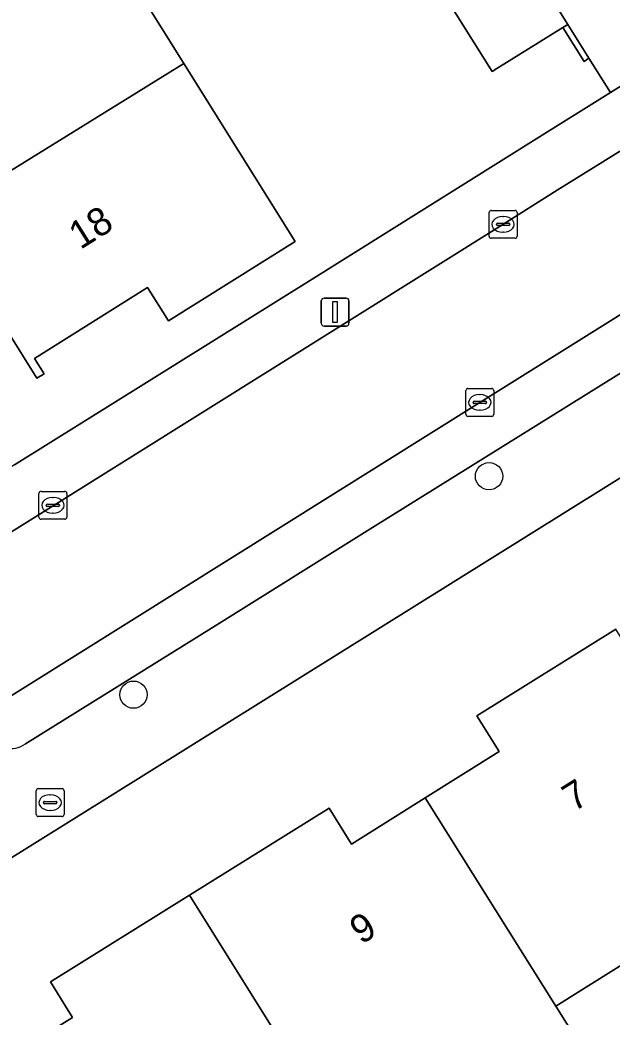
# Model space of a CAD drawing. Extents: x 158835 to 160077, y 386387 to 387778.
# Drawn here: x 159068.07 to 159089.27, y 387041.53 to 387077.25 of the extents above; entities that cross this region are included whole.
import ezdxf

# ---------------------------------------------------------------- set-up
doc = ezdxf.new("R2010")
doc.units = 0
for name, color, linetype in [('IMGEO_Boom', 7, 'Continuous'), ('IMGEO_Brandkraan', 7, 'Continuous'), ('IMGEO_Erf', 7, 'Continuous'), ('IMGEO_Kolk', 7, 'Continuous'), ('IMGEO_Lichtmast', 7, 'Continuous'), ('IMGEO_Muur', 7, 'Continuous'), ('IMGEO_Pand', 7, 'Continuous'), ('IMGEO_Pand_nummerreeks', 7, 'Continuous'), ('IMGEO_Parkeervlak_open', 7, 'Continuous'), ('IMGEO_Rijbaan_lokaal_open', 7, 'Continuous'), ('IMGEO_Voetpad_open', 7, 'Continuous')]:
    doc.layers.add(name, color=color, linetype=linetype)

msp = doc.modelspace()

# ---------------------------------------------------------------- linework, layer by layer
at = {"layer": 'IMGEO_Boom'}
for centre in [(159084.862, 387060.901), (159072.133, 387053.077)]:
    msp.add_circle(centre, 0.489, dxfattribs=at)
at = {"layer": 'IMGEO_Brandkraan'}
for p, q in [((159068.649, 387048.786), (159068.649, 387049.638)), ((159068.724, 387049.712), (159069.576, 387049.712)), ((159069.137, 387049.492), (159069.162, 387049.492)), ((159069.65, 387049.638), (159069.65, 387048.786)), ((159068.908, 387049.206), (159068.908, 387049.218)), ((159069.346, 387049.169), (159068.948, 387049.169)), ((159068.951, 387049.255), (159069.349, 387049.255)), ((159069.392, 387049.218), (159069.392, 387049.206)), ((159069.16, 387048.932), (159069.135, 387048.932)), ((159069.576, 387048.712), (159068.724, 387048.712))]:
    msp.add_line(p, q, dxfattribs=at)
for points in [[(159068.649, 387048.786), (159068.649, 387049.638)], [(159068.724, 387049.712), (159069.576, 387049.712)], [(159069.65, 387049.638), (159069.65, 387048.786)], [(159069.576, 387048.712), (159068.724, 387048.712)]]:
    msp.add_lwpolyline(points, dxfattribs=at)
for centre, radius, start, end in [((159068.726, 387049.636), 0.0765, 91.552, 178.448), ((159068.726, 387049.636), 0.0765, 91.552, 178.448), ((159069.574, 387049.636), 0.0765, 1.552, 88.448), ((159069.574, 387049.636), 0.0765, 1.552, 88.448), ((159068.948, 387049.215), 0.0403, 85.8775, 175.7526), ((159068.945, 387049.205), 0.0366, 178.938, 274.7102), ((159069.349, 387049.212), 0.043, 264.8664, 352.4533), ((159069.353, 387049.217), 0.0386, 1.7309, 96.639), ((159068.726, 387048.788), 0.0765, 181.552, 268.448), ((159068.726, 387048.788), 0.0765, 181.552, 268.448), ((159069.574, 387048.788), 0.0765, 271.552, 358.448), ((159069.574, 387048.788), 0.0765, 271.552, 358.448)]:
    msp.add_arc(centre, radius, start, end, dxfattribs=at)
for centre, major_axis, ratio, start_param, end_param in [((159069.136, 387049.212), (-0.387, 0.002), 0.722429, 4.712389, 7.853982), ((159069.161, 387049.212), (-0.39, 0.002), 0.717154, 1.570796, 4.712389)]:
    msp.add_ellipse(centre, major_axis=major_axis, ratio=ratio, start_param=start_param, end_param=end_param, dxfattribs=at)
at = {"layer": 'IMGEO_Erf'}
for points in [[(159067.868, 387061.308), (159078.525, 387067.969), (159086.674, 387073.064), (159089.207, 387074.648), (159088.441, 387075.876), (159088.263, 387075.765), (159087.506, 387076.978), (159085.147, 387075.505), (159084.978, 387075.399), (159081.697, 387080.65), (159084.403, 387082.34), (159074.494, 387097.991), (159071.028, 387103.53), (159070.62, 387104.158), (159061.621, 387118.5)], [(159069.015, 387083.564), (159073.932, 387075.693), (159077.921, 387069.308), (159073.386, 387066.475), (159072.636, 387067.668), (159068.594, 387065.126), (159068.939, 387064.576), (159068.677, 387064.411), (159065.13, 387070.084), (159064.091, 387069.434), (159064.021, 387069.549), (159063.927, 387069.706), (159064.962, 387070.353), (159060.221, 387077.938)], [(159110.736, 387074.06), (159063.193, 387044.393)], [(159062.71, 387041.605), (159065.419, 387037.291), (159067.725, 387038.732), (159067.005, 387039.886), (159067.275, 387040.054), (159067.37, 387039.902), (159069.951, 387041.51), (159069.158, 387042.784), (159074.14, 387045.892), (159079.133, 387049.006), (159079.934, 387047.727), (159082.578, 387049.382), (159085.221, 387051.036), (159084.42, 387052.315), (159089.398, 387055.425)], [(159094.861, 387046.679), (159087.251, 387041.923), (159088.84, 387039.38), (159081.208, 387034.61), (159079.6, 387037.141), (159071.774, 387032.25), (159071.762, 387032.269), (159069.441, 387030.819), (159076.524, 387019.468), (159125.496, 386940.988)]]:
    msp.add_lwpolyline(points, dxfattribs=at)
at = {"layer": 'IMGEO_Kolk'}
for p, q in [((159084.865, 387069.501), (159084.865, 387070.353)), ((159084.94, 387070.427), (159085.792, 387070.427)), ((159085.353, 387070.207), (159085.378, 387070.207)), ((159085.866, 387070.353), (159085.866, 387069.501)), ((159085.124, 387069.921), (159085.124, 387069.933)), ((159085.562, 387069.884), (159085.164, 387069.884)), ((159085.167, 387069.97), (159085.565, 387069.97)), ((159085.608, 387069.933), (159085.608, 387069.921)), ((159085.376, 387069.647), (159085.351, 387069.647)), ((159085.792, 387069.427), (159084.94, 387069.427)), ((159084.032, 387063.122), (159084.032, 387063.974)), ((159084.107, 387064.048), (159084.959, 387064.048)), ((159084.52, 387063.828), (159084.545, 387063.828)), ((159085.033, 387063.974), (159085.033, 387063.122)), ((159084.291, 387063.542), (159084.291, 387063.554)), ((159084.729, 387063.505), (159084.331, 387063.505)), ((159084.334, 387063.591), (159084.732, 387063.591)), ((159084.775, 387063.554), (159084.775, 387063.542)), ((159084.959, 387063.048), (159084.107, 387063.048)), ((159084.543, 387063.268), (159084.518, 387063.268)), ((159068.747, 387059.436), (159068.747, 387060.288)), ((159068.822, 387060.362), (159069.674, 387060.362)), ((159069.748, 387060.288), (159069.748, 387059.436)), ((159069.006, 387059.856), (159069.006, 387059.868)), ((159069.049, 387059.905), (159069.447, 387059.905)), ((159069.235, 387060.142), (159069.26, 387060.142)), ((159069.49, 387059.868), (159069.49, 387059.856)), ((159069.444, 387059.819), (159069.046, 387059.819)), ((159069.258, 387059.582), (159069.233, 387059.582)), ((159069.674, 387059.362), (159068.822, 387059.362))]:
    msp.add_line(p, q, dxfattribs=at)
for points in [[(159084.865, 387069.501), (159084.865, 387070.353)], [(159084.94, 387070.427), (159085.792, 387070.427)], [(159085.866, 387070.353), (159085.866, 387069.501)], [(159085.792, 387069.427), (159084.94, 387069.427)], [(159084.032, 387063.122), (159084.032, 387063.974)], [(159084.107, 387064.048), (159084.959, 387064.048)], [(159085.033, 387063.974), (159085.033, 387063.122)], [(159084.959, 387063.048), (159084.107, 387063.048)], [(159068.747, 387059.436), (159068.747, 387060.288)], [(159068.822, 387060.362), (159069.674, 387060.362)], [(159069.748, 387060.288), (159069.748, 387059.436)], [(159069.674, 387059.362), (159068.822, 387059.362)]]:
    msp.add_lwpolyline(points, dxfattribs=at)
for centre, radius, start, end in [((159084.942, 387070.351), 0.0765, 91.552, 178.448), ((159084.942, 387070.351), 0.0765, 91.552, 178.448), ((159085.79, 387070.351), 0.0765, 1.552, 88.448), ((159085.79, 387070.351), 0.0765, 1.552, 88.448), ((159085.164, 387069.93), 0.0403, 85.8775, 175.7526), ((159085.161, 387069.92), 0.0366, 178.938, 274.7102), ((159085.565, 387069.927), 0.043, 264.8664, 352.4533), ((159085.569, 387069.932), 0.0386, 1.7309, 96.639), ((159084.942, 387069.503), 0.0765, 181.552, 268.448), ((159084.942, 387069.503), 0.0765, 181.552, 268.448), ((159085.79, 387069.503), 0.0765, 271.552, 358.448), ((159085.79, 387069.503), 0.0765, 271.552, 358.448), ((159084.109, 387063.972), 0.0765, 91.552, 178.448), ((159084.109, 387063.972), 0.0765, 91.552, 178.448), ((159084.957, 387063.972), 0.0765, 1.552, 88.448), ((159084.957, 387063.972), 0.0765, 1.552, 88.448), ((159084.331, 387063.551), 0.0403, 85.8775, 175.7526), ((159084.328, 387063.541), 0.0366, 178.938, 274.7102), ((159084.732, 387063.548), 0.043, 264.8664, 352.4533), ((159084.736, 387063.553), 0.0386, 1.7309, 96.639), ((159084.109, 387063.124), 0.0765, 181.552, 268.448), ((159084.109, 387063.124), 0.0765, 181.552, 268.448), ((159084.957, 387063.124), 0.0765, 271.552, 358.448), ((159084.957, 387063.124), 0.0765, 271.552, 358.448), ((159068.824, 387060.286), 0.0765, 91.552, 178.448), ((159068.824, 387060.286), 0.0765, 91.552, 178.448), ((159069.672, 387060.286), 0.0765, 1.552, 88.448), ((159069.672, 387060.286), 0.0765, 1.552, 88.448), ((159069.046, 387059.865), 0.0403, 85.8775, 175.7526), ((159069.043, 387059.855), 0.0366, 178.938, 274.7102), ((159069.447, 387059.862), 0.043, 264.8664, 352.4533), ((159069.451, 387059.867), 0.0386, 1.7309, 96.639), ((159068.824, 387059.438), 0.0765, 181.552, 268.448), ((159068.824, 387059.438), 0.0765, 181.552, 268.448), ((159069.672, 387059.438), 0.0765, 271.552, 358.448), ((159069.672, 387059.438), 0.0765, 271.552, 358.448)]:
    msp.add_arc(centre, radius, start, end, dxfattribs=at)
for centre, major_axis, ratio, start_param, end_param in [((159085.352, 387069.927), (-0.387, 0.002), 0.722429, 4.712389, 7.853982), ((159085.377, 387069.927), (-0.39, 0.002), 0.717154, 1.570796, 4.712389), ((159084.519, 387063.548), (-0.387, 0.002), 0.722429, 4.712389, 7.853982), ((159084.544, 387063.548), (-0.39, 0.002), 0.717154, 1.570796, 4.712389), ((159069.234, 387059.862), (-0.387, 0.002), 0.722429, 4.712389, 7.853982), ((159069.259, 387059.862), (-0.39, 0.002), 0.717154, 1.570796, 4.712389)]:
    msp.add_ellipse(centre, major_axis=major_axis, ratio=ratio, start_param=start_param, end_param=end_param, dxfattribs=at)
at = {"layer": 'IMGEO_Lichtmast'}
for p, q in [((159078.855, 387066.383), (159078.855, 387067.183)), ((159078.855, 387067.183), (159078.855, 387066.383)), ((159078.955, 387067.283), (159079.745, 387067.283)), ((159079.745, 387067.283), (159078.955, 387067.283)), ((159079.845, 387067.183), (159079.845, 387066.383)), ((159079.845, 387066.383), (159079.845, 387067.183)), ((159079.745, 387066.283), (159078.955, 387066.283)), ((159078.955, 387066.283), (159079.745, 387066.283))]:
    msp.add_line(p, q, dxfattribs=at)
msp.add_lwpolyline([(159079.275, 387067.158), (159079.425, 387067.158), (159079.425, 387066.408), (159079.275, 387066.408), (159079.275, 387067.158)], dxfattribs=at)
for centre, start, end in [((159078.955, 387067.183), 90, 180), ((159078.955, 387067.183), 90, 180), ((159079.745, 387067.183), 0, 90), ((159079.745, 387067.183), 360, 90), ((159078.955, 387066.383), 180, 270), ((159078.955, 387066.383), 180, 270), ((159079.745, 387066.383), 270, 0), ((159079.745, 387066.383), 270, 0)]:
    msp.add_arc(centre, 0.1, start, end, dxfattribs=at)
at = {"layer": 'IMGEO_Muur'}
msp.add_lwpolyline([(159087.506, 387076.978), (159088.263, 387075.765), (159088.441, 387075.876), (159087.684, 387077.089)], close=True, dxfattribs=at)
msp.add_lwpolyline([(159078.525, 387067.969), (159086.674, 387073.064)], dxfattribs=at)
at = {"layer": 'IMGEO_Pand'}
for points in [[(159073.932, 387075.693), (159069.015, 387083.564), (159059.111, 387077.412), (159059.184, 387077.29), (159060.221, 387077.938), (159064.962, 387070.353), (159063.927, 387069.706), (159064.021, 387069.549)], [(159087.684, 387077.089), (159084.403, 387082.34), (159081.697, 387080.65), (159084.978, 387075.399), (159085.147, 387075.505), (159087.506, 387076.978)], [(159064.021, 387069.549), (159064.091, 387069.434), (159065.13, 387070.084), (159068.677, 387064.411), (159068.939, 387064.576), (159068.594, 387065.126), (159072.636, 387067.668), (159073.386, 387066.475), (159077.921, 387069.308), (159073.932, 387075.693)], [(159087.251, 387041.923), (159094.861, 387046.679), (159089.398, 387055.425), (159084.42, 387052.315), (159085.221, 387051.036), (159082.578, 387049.382)], [(159079.6, 387037.141), (159081.208, 387034.61), (159088.84, 387039.38), (159087.251, 387041.923), (159082.578, 387049.382), (159079.934, 387047.727), (159079.133, 387049.006), (159074.14, 387045.892)], [(159069.441, 387030.819), (159071.762, 387032.269), (159071.774, 387032.25), (159079.6, 387037.141), (159074.14, 387045.892), (159069.158, 387042.784), (159069.951, 387041.51), (159067.37, 387039.902), (159067.275, 387040.054), (159067.005, 387039.886), (159067.725, 387038.732), (159065.419, 387037.291)]]:
    msp.add_lwpolyline(points, close=True, dxfattribs=at)
at = {"layer": 'IMGEO_Parkeervlak_open'}
for points in [[(159110.593, 387079.859), (159103.151, 387075.188), (159084.528, 387063.55), (159066.593, 387052.325), (159064.66, 387051.128)], [(159068.268, 387051.318), (159074.93, 387055.455), (159080.693, 387059.061), (159090.042, 387064.897), (159095.791, 387068.486), (159105.146, 387074.32), (159108.343, 387076.314), (159108.9, 387076.666)]]:
    msp.add_lwpolyline(points, dxfattribs=at)
msp.add_arc((159067.731, 387052.067), 0.922, 256.753, 305.631, dxfattribs=at)
at = {"layer": 'IMGEO_Rijbaan_lokaal_open'}
msp.add_lwpolyline([(159140.304, 387104.262), (159137.382, 387102.443), (159121.021, 387092.233), (159104.81, 387082.095), (159090.415, 387073.084), (159087.209, 387071.089), (159085.362, 387069.926), (159066.482, 387058.108), (159057.993, 387052.813), (159060.695, 387048.588), (159061.454, 387049.086), (159064.66, 387051.128), (159066.593, 387052.325), (159084.528, 387063.55), (159103.151, 387075.188), (159110.593, 387079.859), (159110.704, 387079.928), (159119.193, 387085.238), (159119.416, 387085.378), (159123.735, 387088.075), (159139.7, 387098.006), (159145.108, 387101.404), (159145.475, 387101.632), (159152.358, 387105.91)], dxfattribs=at)
at = {"layer": 'IMGEO_Voetpad_open'}
for points in [[(159143.08, 387108.388), (159140.091, 387106.463), (159092.005, 387076.397), (159089.207, 387074.648), (159086.674, 387073.064), (159078.525, 387067.969), (159067.868, 387061.308), (159063.036, 387058.319), (159058.826, 387055.683), (159056.14, 387053.974), (159055.192, 387053.386), (159050.577, 387050.525), (159048.428, 387049.192), (159052.552, 387042.529), (159052.677, 387042.36)], [(159058.932, 387041.754), (159063.193, 387044.393), (159110.736, 387074.06), (159110.756, 387074.075), (159115.626, 387077.064), (159119.918, 387079.72), (159122.014, 387081.038), (159141.336, 387093.187)], [(159054.603, 387050.681), (159056.255, 387051.72), (159057.993, 387052.813), (159057.411, 387053.746), (159065.9, 387059.041), (159066.482, 387058.108), (159085.362, 387069.926), (159087.209, 387071.089), (159090.415, 387073.084), (159104.81, 387082.095)], [(159108.9, 387076.666), (159108.343, 387076.314), (159105.146, 387074.32), (159095.791, 387068.486), (159090.042, 387064.897), (159080.693, 387059.061), (159074.93, 387055.455), (159068.268, 387051.318)]]:
    msp.add_lwpolyline(points, dxfattribs=at)
msp.add_lwpolyline([(159074.287, 387104.756), (159073.536, 387105.956), (159070.62, 387104.158), (159071.028, 387103.53), (159074.494, 387097.991), (159084.403, 387082.34), (159087.684, 387077.089), (159088.441, 387075.876), (159089.207, 387074.648), (159092.005, 387076.397), (159091.25, 387077.595), (159090.605, 387078.618), (159085.842, 387086.241), (159077.522, 387099.573)], close=True, dxfattribs=at)
msp.add_arc((159067.731, 387052.067), 0.922, 256.753, 305.631, dxfattribs=at)

# ---------------------------------------------------------------- texts
at = {"layer": 'IMGEO_Pand_nummerreeks'}
for s, rotation, p in [('18', 32.1656, (159070.231, 387069.005)), ('7', 32.0045, (159087.895, 387048.862)), ('9', 32.0045, (159080.287, 387044.107))]:
    msp.add_text(s, height=1, rotation=rotation, dxfattribs=at).set_placement(p)

doc.saveas('drawing.dxf')
